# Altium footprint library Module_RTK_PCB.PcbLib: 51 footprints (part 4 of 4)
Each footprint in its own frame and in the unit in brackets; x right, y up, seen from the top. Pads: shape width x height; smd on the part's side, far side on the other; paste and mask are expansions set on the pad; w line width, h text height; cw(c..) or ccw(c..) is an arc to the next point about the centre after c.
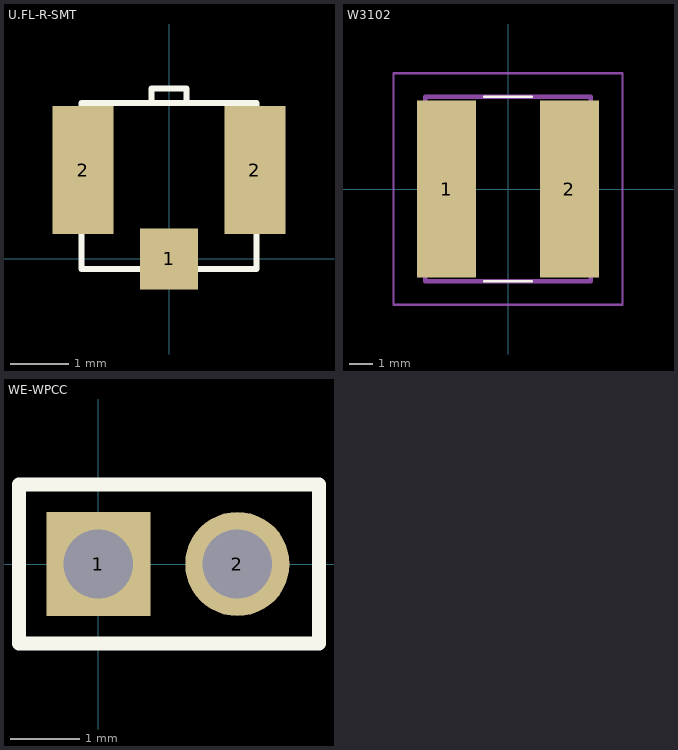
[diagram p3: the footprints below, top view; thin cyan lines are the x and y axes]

## U.FL-R-SMT [mm]
height 4.8
pads (3):
  rect 1x1.05 smd: 1(0,0)
  rect 1.05x2.2 smd: 2(-1.475,1.525) 2(1.475,1.525)
Top Overlay:
  lines w0.1: -0.3,2.675 -0.3,2.925 0.3,2.925 0.3,2.675 ; -1.5,-0.175 1.5,-0.175 1.5,2.675 -1.5,2.675 -1.5,-0.175

## W3102 [mm]
pads (2):
  rect 2.5x7.5 smd: 1(-2.6,0) 2(2.6,0)
Top Overlay:
  lines w0.1: -1,-3.9 1,-3.9 ; -1,3.9 1,3.9
Mechanical 13:
  lines w0.2: -3.5,-3.9 3.5,-3.9 3.5,3.9 -3.5,3.9 -3.5,-3.9
Mechanical 15:
  lines w0.1: -4.85,-4.9 4.85,-4.9 4.85,4.9 -4.85,4.9 -4.85,-4.9
3D body "W3102.stp": height 5.45, standoff 0, extent -3.6,-3.9 3.6,3.9

## WE-WPCC [mm] "Wireless Power Charging  Receiver Coil"
pads (2):
  rect 1.5x1.5 hole 1: 1(0,0)
  round 1.5 hole 1: 2(2,0)
Top Overlay:
  lines w0.2: -1.143,-1.143 3.175,-1.143 3.175,1.143 -1.143,1.143 -1.143,-1.143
